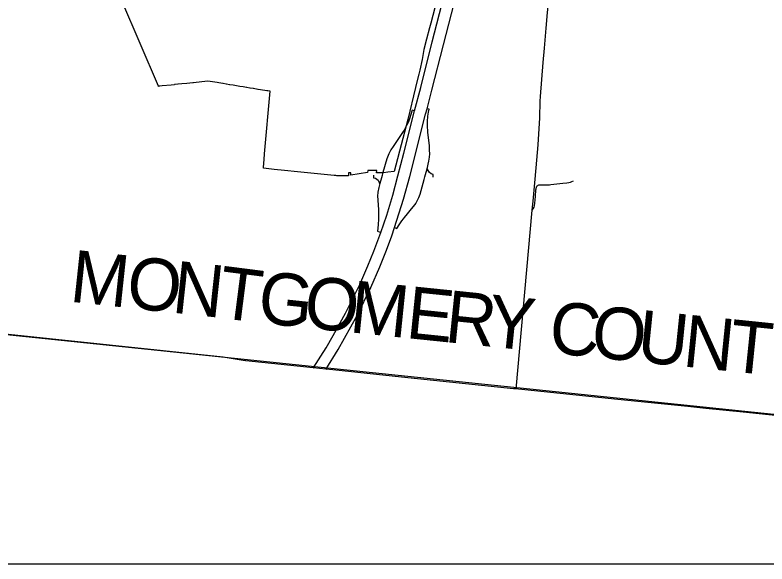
# Model space of a CAD drawing. Extents: x 0 to 34, y 0 to 22.
# Drawn here: x 4.9539 to 5.1855, y 14.1 to 14.2693 of the extents above; entities that cross this region are included whole.
import ezdxf

# ---------------------------------------------------------------- set-up
doc = ezdxf.new("R2010")
doc.units = 0
for name, color, linetype in [('GM_X_Corporation', 7, 'Continuous'), ('GM_X_County', 7, 'Continuous'), ('GM_X_County_Text', 7, 'Continuous'), ('GM_X_Interchange_Ramps', 7, 'Continuous'), ('GM_X_Interstate_Route', 7, 'Continuous'), ('GM_X_State_Route', 7, 'Continuous'), ('SC_Scratch1', 7, 'Continuous'), ('SH_Data', 7, 'Continuous')]:
    doc.layers.add(name, color=color, linetype=linetype)

msp = doc.modelspace()

# ---------------------------------------------------------------- linework, layer by layer
at = {"layer": 'GM_X_Corporation'}
msp.add_lwpolyline([(5.083842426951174, 14.273905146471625), (5.081903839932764, 14.266766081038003), (5.081521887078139, 14.265359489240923), (5.080569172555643, 14.26185101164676), (5.080096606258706, 14.259923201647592), (5.080072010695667, 14.259822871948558), (5.079848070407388, 14.25867388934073), (5.079839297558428, 14.25862885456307), (5.0792475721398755, 14.255592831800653), (5.078606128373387, 14.252301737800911), (5.078280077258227, 14.25101147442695), (5.07726519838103, 14.246995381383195), (5.077259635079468, 14.246973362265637), (5.074850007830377, 14.237023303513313), (5.073340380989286, 14.23118629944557), (5.070684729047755, 14.221014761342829), (5.068736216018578, 14.220805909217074), (5.067417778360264, 14.220667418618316), (5.065237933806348, 14.220665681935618), (5.065330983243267, 14.221325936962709), (5.062543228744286, 14.221338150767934), (5.062481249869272, 14.220687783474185), (5.057347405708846, 14.219944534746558), (5.057345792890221, 14.220581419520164), (5.056549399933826, 14.220570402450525), (5.056551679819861, 14.21968568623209), (5.054128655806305, 14.219697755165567), (5.05364975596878, 14.21970831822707), (5.053345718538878, 14.219723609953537), (5.053034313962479, 14.21973989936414), (5.052638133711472, 14.219766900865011), (5.052189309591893, 14.219805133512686), (5.040841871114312, 14.2209751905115), (5.036826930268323, 14.221380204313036), (5.03366338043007, 14.221638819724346), (5.032001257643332, 14.221817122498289), (5.0303676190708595, 14.222021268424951), (5.030384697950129, 14.222218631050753), (5.030394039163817, 14.222326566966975), (5.0305999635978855, 14.22470575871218), (5.030749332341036, 14.226431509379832), (5.03242164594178, 14.245752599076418), (5.031703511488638, 14.245857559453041), (5.0317045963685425, 14.24586462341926), (5.031510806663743, 14.245896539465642), (5.031457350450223, 14.245905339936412), (5.029528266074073, 14.246223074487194), (5.029474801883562, 14.246231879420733), (5.028735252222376, 14.246353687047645), (5.028681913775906, 14.246362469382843), (5.027308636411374, 14.246588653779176), (5.027261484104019, 14.246596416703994), (5.026261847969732, 14.246761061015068), (5.026213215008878, 14.246769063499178), (5.025230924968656, 14.246930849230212), (5.025182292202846, 14.246938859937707), (5.024184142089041, 14.247103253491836), (5.0241355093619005, 14.247111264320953), (5.023153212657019, 14.247273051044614), (5.023104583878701, 14.247281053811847), (5.022106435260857, 14.247445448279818), (5.022057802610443, 14.247453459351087), (5.02107551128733, 14.24761523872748), (5.021026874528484, 14.247623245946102), (5.020028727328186, 14.247787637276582), (5.01998008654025, 14.247795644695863), (5.018997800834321, 14.247957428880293), (5.0189491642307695, 14.247965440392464), (5.0179510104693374, 14.248129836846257), (5.017902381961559, 14.248137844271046), (5.016643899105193, 14.24834508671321), (5.01660061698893, 14.248352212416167), (5.016096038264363, 14.248435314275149), (5.013285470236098, 14.248898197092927), (5.011438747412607, 14.248702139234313), (5.008804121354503, 14.248422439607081), (5.008734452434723, 14.24841504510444), (5.008590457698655, 14.248399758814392), (5.006837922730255, 14.24821371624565), (5.006780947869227, 14.248207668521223), (5.005290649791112, 14.248049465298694), (5.0052455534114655, 14.248044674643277), (5.004077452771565, 14.247920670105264), (5.0040367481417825, 14.247916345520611), (5.003038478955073, 14.247810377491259), (5.002997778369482, 14.247806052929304), (5.001999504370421, 14.247700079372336), (5.00195880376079, 14.247695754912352), (4.999170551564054, 14.247399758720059), (4.998467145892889, 14.247325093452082), (4.998439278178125, 14.247322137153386), (4.998337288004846, 14.247311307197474), (4.998280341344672, 14.247305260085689), (4.998037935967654, 14.24727953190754), (4.9980180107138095, 14.247326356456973), (4.986802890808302, 14.273682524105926)], dxfattribs=at)
at = {"layer": 'GM_X_County'}
msp.add_lwpolyline([(5.19105433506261, 14.145467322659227), (5.17815238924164, 14.146790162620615), (5.166631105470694, 14.147971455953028), (5.161104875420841, 14.148537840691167), (5.139590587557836, 14.150743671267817), (5.108966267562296, 14.153883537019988), (5.108172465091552, 14.153964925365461), (5.107380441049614, 14.154047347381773), (5.0729196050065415, 14.157633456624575), (5.051743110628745, 14.159837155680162), (5.049621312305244, 14.160057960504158), (5.04570617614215, 14.16046535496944), (5.0249840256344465, 14.162621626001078), (5.024822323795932, 14.162638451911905), (5.024115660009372, 14.162712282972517), (5.017995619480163, 14.163757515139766), (4.929360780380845, 14.173144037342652)], dxfattribs=at)
at = {"layer": 'GM_X_Interchange_Ramps'}
for points in [[(5.076958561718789, 14.239690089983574), (5.076245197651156, 14.239900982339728), (5.075797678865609, 14.238595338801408), (5.0753695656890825, 14.237310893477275), (5.075034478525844, 14.236361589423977), (5.074494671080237, 14.235207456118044), (5.074154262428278, 14.234558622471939)], [(5.080988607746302, 14.233635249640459), (5.080940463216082, 14.234659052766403), (5.080921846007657, 14.236446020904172), (5.081014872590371, 14.238046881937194), (5.081201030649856, 14.239294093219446), (5.081424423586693, 14.240262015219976), (5.080782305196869, 14.240385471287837)], [(5.074154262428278, 14.234558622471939), (5.073898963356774, 14.234071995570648), (5.07304273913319, 14.232768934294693), (5.070306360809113, 14.228766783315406), (5.069599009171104, 14.227668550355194)], [(5.0801441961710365, 14.219385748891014), (5.080329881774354, 14.220121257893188), (5.080804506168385, 14.221820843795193), (5.081331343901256, 14.224197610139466), (5.081517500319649, 14.225482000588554), (5.081647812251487, 14.226468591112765), (5.081591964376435, 14.227622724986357), (5.081498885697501, 14.229056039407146), (5.0810148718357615, 14.233076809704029), (5.080988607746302, 14.233635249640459)], [(5.069599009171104, 14.227668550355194), (5.068984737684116, 14.226458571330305), (5.06842626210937, 14.224932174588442), (5.067125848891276, 14.220705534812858)], [(5.067125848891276, 14.220705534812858), (5.067044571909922, 14.220441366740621), (5.066981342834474, 14.219838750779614)], [(5.082672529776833, 14.21932810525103), (5.082687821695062, 14.220136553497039), (5.082044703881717, 14.220335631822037), (5.081585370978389, 14.220718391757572), (5.0811719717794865, 14.22130023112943), (5.081049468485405, 14.221774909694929), (5.080804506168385, 14.221820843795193)], [(5.064256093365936, 14.219876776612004), (5.06426669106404, 14.219051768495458), (5.0648960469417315, 14.218945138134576), (5.065322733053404, 14.21871045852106), (5.0656961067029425, 14.218369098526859), (5.065962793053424, 14.217846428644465), (5.066048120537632, 14.217441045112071), (5.06628902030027, 14.217370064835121)], [(5.066981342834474, 14.219838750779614), (5.066788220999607, 14.219063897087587), (5.06628902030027, 14.217370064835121), (5.065898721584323, 14.216045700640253), (5.065605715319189, 14.214650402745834), (5.065535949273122, 14.21342249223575), (5.065591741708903, 14.21233417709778), (5.065603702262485, 14.212157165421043)], [(5.078453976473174, 14.2135368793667), (5.078635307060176, 14.214048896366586), (5.079902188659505, 14.218603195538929), (5.0801441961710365, 14.219385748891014)], [(5.113185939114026, 14.209095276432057), (5.113509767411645, 14.209544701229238), (5.113771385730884, 14.210015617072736), (5.113893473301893, 14.210486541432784), (5.113980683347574, 14.21121908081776), (5.114155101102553, 14.213329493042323), (5.114329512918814, 14.215405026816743), (5.114364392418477, 14.215705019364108), (5.114397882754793, 14.215880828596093), (5.114464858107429, 14.216098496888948), (5.114540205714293, 14.21625756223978), (5.114632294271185, 14.216408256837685), (5.114757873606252, 14.216567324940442), (5.114891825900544, 14.216692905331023), (5.115042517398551, 14.216801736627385), (5.115235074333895, 14.216893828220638), (5.11545274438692, 14.2169608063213), (5.1156787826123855, 14.216969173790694), (5.1160220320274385, 14.216960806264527), (5.116834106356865, 14.21693568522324), (5.117713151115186, 14.216910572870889), (5.11817360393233, 14.216910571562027), (5.118508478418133, 14.216927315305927), (5.118960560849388, 14.216977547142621), (5.119831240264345, 14.217078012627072), (5.122610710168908, 14.217387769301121), (5.12380788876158, 14.217546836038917), (5.12447764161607, 14.21766404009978), (5.125005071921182, 14.217789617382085), (5.12542366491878, 14.217948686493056), (5.125910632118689, 14.21819206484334)], [(5.077296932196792, 14.211181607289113), (5.077781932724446, 14.211979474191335), (5.07827264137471, 14.213024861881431), (5.078453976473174, 14.2135368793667)], [(5.065603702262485, 14.212157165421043), (5.065801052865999, 14.209236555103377), (5.065870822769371, 14.207938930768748), (5.0658708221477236, 14.206473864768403), (5.0657591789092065, 14.204576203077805), (5.065494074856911, 14.202622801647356), (5.066564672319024, 14.20225649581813)], [(5.073513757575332, 14.206383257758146), (5.07387776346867, 14.206859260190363), (5.0747525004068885, 14.207989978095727), (5.076011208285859, 14.20952608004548), (5.07712056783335, 14.2108914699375), (5.077296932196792, 14.211181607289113)], [(5.07078763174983, 14.203715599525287), (5.071488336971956, 14.203403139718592), (5.072171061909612, 14.204576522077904), (5.073045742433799, 14.205771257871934), (5.073513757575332, 14.206383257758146)]]:
    msp.add_lwpolyline(points, dxfattribs=at)
at = {"layer": 'GM_X_Interstate_Route'}
for points in [[(5.07078763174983, 14.203715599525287), (5.073535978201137, 14.2125255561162), (5.075439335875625, 14.219517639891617), (5.080344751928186, 14.238717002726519), (5.080782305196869, 14.240385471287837), (5.082299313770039, 14.246144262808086), (5.085891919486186, 14.260049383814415), (5.09318887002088, 14.288418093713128), (5.09735856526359, 14.304575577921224), (5.101453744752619, 14.320007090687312)], [(5.045725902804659, 14.160420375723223), (5.04967747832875, 14.166620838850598), (5.051911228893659, 14.170432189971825), (5.055707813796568, 14.177374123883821), (5.060045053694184, 14.186197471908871), (5.062558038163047, 14.191949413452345), (5.064438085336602, 14.196491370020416), (5.066564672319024, 14.20225649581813), (5.068379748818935, 14.207518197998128), (5.070197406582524, 14.21368485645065), (5.071786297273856, 14.219656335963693), (5.073643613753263, 14.226715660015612), (5.076958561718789, 14.239690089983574), (5.078902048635, 14.246932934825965), (5.082392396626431, 14.261035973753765), (5.089745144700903, 14.289646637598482)], [(5.049641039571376, 14.160012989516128), (5.053436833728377, 14.166168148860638), (5.0592632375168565, 14.176629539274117), (5.063432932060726, 14.185248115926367), (5.066225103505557, 14.19165155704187), (5.0683099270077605, 14.19677055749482), (5.0699107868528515, 14.201163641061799), (5.07078763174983, 14.203715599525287)]]:
    msp.add_lwpolyline(points, dxfattribs=at)
at = {"layer": 'GM_X_State_Route'}
for p, q in [((5.114054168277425, 14.218688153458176), (5.114581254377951, 14.224536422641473)), ((5.113439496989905, 14.211896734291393), (5.114054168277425, 14.218688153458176))]:
    msp.add_line(p, q, dxfattribs=at)
for points in [[(5.114581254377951, 14.224536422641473), (5.1150045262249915, 14.229232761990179), (5.115486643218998, 14.237562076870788), (5.115654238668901, 14.242716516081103), (5.115700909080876, 14.244150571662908), (5.116584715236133, 14.254649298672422), (5.116956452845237, 14.259099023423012), (5.1174685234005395, 14.265228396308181), (5.1179238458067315, 14.27002243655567), (5.118459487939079, 14.274736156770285), (5.119605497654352, 14.283340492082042), (5.120393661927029, 14.289900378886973)], [(5.108192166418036, 14.153919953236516), (5.113185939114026, 14.209095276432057), (5.113439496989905, 14.211896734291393)]]:
    msp.add_lwpolyline(points, dxfattribs=at)
at = {"layer": 'SC_Scratch1'}
msp.add_lwpolyline([(5.5712702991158, 14.106219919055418), (4.853299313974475, 14.180865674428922), (3.9803362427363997, 14.19875001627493)], dxfattribs=at)
at = {"layer": 'SH_Data'}
msp.add_line((2.1, 14.1), (8.899999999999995, 14.1), dxfattribs=at)

# ---------------------------------------------------------------- texts
at = {"layer": 'GM_X_County_Text'}
for s, height, rotation, p in [('M', 0.016074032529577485, 353.896972, (4.970373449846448, 14.180927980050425)), ('O', 0.016074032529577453, 353.890367, (4.987743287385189, 14.17907075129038)), ('N', 0.016074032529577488, 353.766683, (5.001869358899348, 14.177558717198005)), ('T', 0.016074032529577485, 352.708498, (5.0159231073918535, 14.176024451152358)), ('G', 0.016074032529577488, 353.97398699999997, (5.028234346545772, 14.1744536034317)), ('O', 0.016074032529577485, 354.127015, (5.042418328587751, 14.172956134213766)), ('M', 0.016074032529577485, 354.132278, (5.0565609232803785, 14.171501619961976)), ('E', 0.016074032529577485, 354.134003, (5.073939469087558, 14.169715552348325)), ('R', 0.016074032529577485, 354.134731, (5.085899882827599, 14.168486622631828)), ('Y', 0.016074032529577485, 354.133059, (5.09891556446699, 14.16714952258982)), ('C', 0.016074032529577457, 354.134585, (5.117912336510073, 14.165197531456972)), ('O', 0.016074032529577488, 354.13414, (5.130928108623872, 14.163860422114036)), ('U', 0.016074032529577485, 354.133059, (5.145069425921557, 14.162407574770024)), ('N', 0.016074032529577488, 354.13433399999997, (5.159211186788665, 14.160954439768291)), ('T', 0.016074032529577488, 354.13346, (5.173352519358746, 14.159501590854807))]:
    msp.add_text(s, height=height, rotation=rotation, dxfattribs=at).set_placement(p)

doc.saveas('drawing.dxf')
